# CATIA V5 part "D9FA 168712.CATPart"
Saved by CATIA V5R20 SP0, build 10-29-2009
Part number: D9FA 168712
Revision: ANY
Definition: UNKNOWN
Nomenclature: D9FA 168712
Source: Unknown
Bounding box of the stored display mesh (mm): x -8 to 8, y 0.13 to 20.13, z -8 to 8
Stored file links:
  C:\Users\Utente\Desktop\IO LAVORO\3D X SITO CF\CUMSA\3D files FA\FA 168712-21\D9FA 168712.CATPart
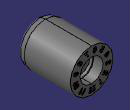
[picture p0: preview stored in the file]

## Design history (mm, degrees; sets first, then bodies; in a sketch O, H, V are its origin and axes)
Body1 "Cortar-Extruir4" (main body)
  Solid1: solid without history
